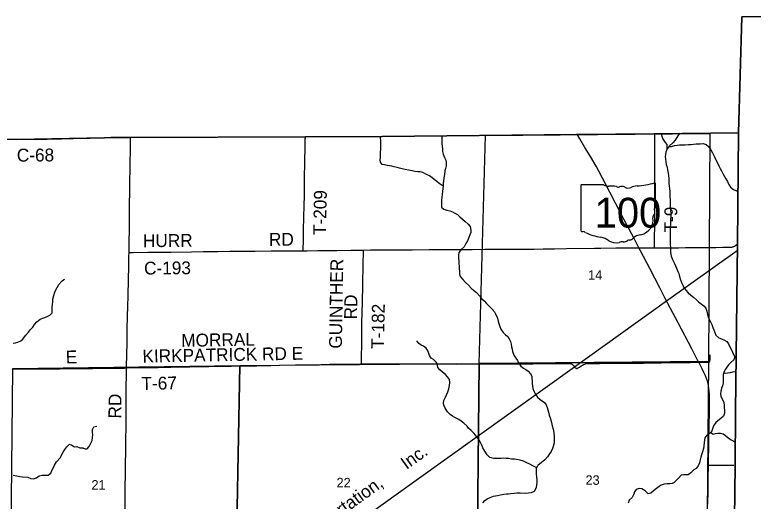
# Model space of a CAD drawing. Extents: x 1584893 to 1934202, y 663575 to 1091909.
# Drawn here: x 1852245 to 1869452, y 976938 to 988278 of the extents above; entities that cross this region are included whole.
import ezdxf

# ---------------------------------------------------------------- set-up
doc = ezdxf.new("R2010")
doc.units = 0
for name, color, linetype in [('GM_X_Adjacent_County', 7, 'Continuous'), ('GM_X_County', 7, 'Continuous'), ('GM_X_County_Road', 7, 'Continuous'), ('GM_X_County_Road_Text', 7, 'Continuous'), ('GM_X_Minor_River', 7, 'Continuous'), ('GM_X_Rail_Line', 7, 'Continuous'), ('GM_X_Rail_Line_Text', 7, 'Continuous'), ('GM_X_Section', 7, 'Continuous'), ('GM_X_Section_Text', 7, 'Continuous'), ('GM_X_State_Location', 7, 'Continuous'), ('GM_X_State_Route', 7, 'Continuous'), ('GM_X_State_Shield', 7, 'Continuous'), ('GM_X_Township', 7, 'Continuous'), ('GM_X_Township_Road', 7, 'Continuous'), ('GM_X_Township_Road_Text', 7, 'Continuous')]:
    doc.layers.add(name, color=color, linetype=linetype)

msp = doc.modelspace()

# ---------------------------------------------------------------- linework, layer by layer
at = {"layer": 'GM_X_Adjacent_County'}
for points in [[(1847071, 963938), (1852487, 963992), (1853408, 964004), (1853786, 964009), (1855618, 964050), (1860298, 964101), (1862894, 964131), (1865546, 964151), (1868643, 964155), (1868654, 967077), (1868896, 971111), (1868903, 971230), (1868993, 974454), (1868995, 974673), (1869028, 977767), (1869041, 979034), (1869083, 982941), (1869110, 985528), (1869183, 988230), (1871661, 988243)], [(1879625, 988278), (1878309, 988257), (1877944, 988247), (1877300, 988258), (1875677, 988261), (1871661, 988243), (1869183, 988230), (1869110, 985528), (1867146, 985506), (1865333, 985487), (1860805, 985437), (1859023, 985435), (1854939, 985417), (1854489, 985417), (1854335, 985412), (1852293, 985374), (1849534, 985395)]]:
    msp.add_lwpolyline(points, dxfattribs=at)
at = {"layer": 'GM_X_County'}
msp.add_lwpolyline([(1849534, 985395), (1852293, 985374), (1854335, 985412), (1854489, 985417), (1854939, 985417), (1859023, 985435), (1860805, 985437), (1865333, 985487), (1867146, 985506), (1869110, 985528), (1869083, 982941), (1869041, 979034), (1869028, 977767), (1868995, 974673)], dxfattribs=at)
at = {"layer": 'GM_X_County_Road'}
for points in [[(1852292, 985375), (1852327, 985375), (1852409, 985376), (1852721, 985377), (1852999, 985381), (1853141, 985382), (1853271, 985385), (1853333, 985387), (1853460, 985391), (1853608, 985395), (1853805, 985401), (1854002, 985405), (1854183, 985408), (1854330, 985410), (1854544, 985418), (1854828, 985423), (1854938, 985423)], [(1854908, 982736), (1854909, 982792), (1854910, 982989), (1854915, 983268), (1854918, 983563), (1854922, 983891), (1854924, 984121), (1854928, 984383), (1854932, 984695), (1854941, 985253), (1854942, 985335), (1854942, 985354), (1854941, 985366), (1854941, 985379), (1854939, 985401), (1854938, 985423)], [(1860368, 982794), (1860536, 982795), (1861062, 982799), (1861505, 982801), (1861899, 982803), (1862112, 982804), (1862408, 982805), (1862670, 982807), (1862900, 982807), (1863196, 982811), (1863622, 982814), (1863967, 982816), (1864345, 982817), (1864558, 982819), (1864820, 982823), (1865099, 982827), (1865756, 982836), (1865904, 982838), (1866248, 982841), (1866482, 982842)], [(1866482, 982842), (1866560, 982842), (1866774, 982843), (1866789, 982843)], [(1866789, 982843), (1866872, 982844), (1867151, 982844), (1867155, 982844)], [(1867155, 982844), (1867315, 982845), (1867709, 982848), (1867873, 982849), (1868004, 982850), (1868217, 982852), (1868316, 982853), (1868398, 982854), (1868577, 982856), (1868734, 982857), (1868874, 982859), (1868923, 982861), (1868953, 982863), (1868968, 982865), (1868988, 982871), (1869003, 982877), (1869020, 982887), (1869035, 982896), (1869076, 982927)], [(1854850, 980044), (1854851, 980102), (1854856, 980331), (1854861, 980659), (1854867, 980932), (1854874, 981268), (1854880, 981463), (1854885, 981742), (1854902, 982431), (1854907, 982644), (1854908, 982736)], [(1854908, 982736), (1854939, 982736), (1855004, 982738), (1855349, 982740), (1855694, 982744), (1855891, 982746), (1856367, 982753), (1856646, 982756), (1856974, 982762), (1857253, 982764), (1857844, 982767), (1858222, 982771), (1858829, 982775), (1858968, 982777)], [(1858968, 982777), (1859059, 982778), (1859305, 982781), (1859748, 982786), (1860077, 982791), (1860368, 982794)], [(1852210, 980019), (1852468, 980021), (1852675, 980022), (1852979, 980025), (1853301, 980027), (1853585, 980030), (1853861, 980034), (1854057, 980035), (1854396, 980038), (1854636, 980041), (1854799, 980042), (1854850, 980044)], [(1854798, 974712), (1854799, 974791), (1854802, 975082), (1854804, 975281), (1854804, 975393), (1854804, 975492), (1854807, 975689), (1854810, 975984), (1854812, 976295), (1854813, 976486), (1854817, 976775), (1854816, 976957), (1854817, 977075), (1854820, 977198), (1854826, 977641), (1854829, 977874), (1854833, 978035), (1854834, 978248), (1854839, 978806), (1854840, 979085), (1854841, 979338), (1854844, 979560), (1854848, 979920), (1854850, 980044)]]:
    msp.add_lwpolyline(points, dxfattribs=at)
at = {"layer": 'GM_X_Minor_River'}
for points in [[(1862225, 984296), (1862202, 984299), (1862133, 984347), (1862078, 984392), (1862021, 984437), (1861970, 984473), (1861907, 984520), (1861838, 984558), (1861753, 984598), (1861695, 984613), (1861635, 984618), (1861570, 984627), (1861508, 984639), (1861428, 984656), (1861345, 984672), (1861271, 984688), (1861213, 984701), (1861158, 984716), (1861086, 984734), (1861034, 984745), (1860979, 984756), (1860923, 984765), (1860861, 984777), (1860809, 984786), (1860765, 984845), (1860762, 984897), (1860767, 984951), (1860768, 985023), (1860771, 985077), (1860773, 985139), (1860774, 985196), (1860775, 985246), (1860774, 985314), (1860768, 985438)], [(1862193, 985454), (1862194, 985336), (1862199, 985276), (1862204, 985206), (1862208, 985152), (1862213, 985087), (1862224, 985025), (1862258, 984954), (1862291, 984887), (1862296, 984831), (1862294, 984755), (1862281, 984697), (1862270, 984637), (1862258, 984555), (1862246, 984477), (1862235, 984405), (1862227, 984337), (1862224, 984285), (1862219, 984225), (1862211, 984155), (1862204, 984095), (1862195, 984019), (1862191, 983967), (1862185, 983858), (1862192, 983796), (1862239, 983743), (1862312, 983719), (1862384, 983704), (1862445, 983683), (1862499, 983653), (1862558, 983618), (1862619, 983571), (1862676, 983511), (1862737, 983462), (1862807, 983398), (1862854, 983345), (1862872, 983257), (1862869, 983204), (1862852, 983145), (1862829, 983085), (1862793, 983008), (1862758, 982942), (1862714, 982871), (1862649, 982804), (1862595, 982735), (1862584, 982673), (1862583, 982605), (1862589, 982534), (1862596, 982478), (1862601, 982416), (1862603, 982360), (1862604, 982292), (1862608, 982223), (1862631, 982167), (1862684, 982107), (1862750, 982036), (1862815, 981972), (1862880, 981903), (1862935, 981859), (1863002, 981806), (1863074, 981728), (1863123, 981667), (1863183, 981606), (1863238, 981546), (1863306, 981479), (1863363, 981425), (1863422, 981352), (1863452, 981291), (1863491, 981202), (1863507, 981138), (1863522, 981081), (1863545, 981012), (1863571, 980952), (1863626, 980874), (1863680, 980817), (1863734, 980778), (1863768, 980725), (1863795, 980662), (1863810, 980600), (1863820, 980537), (1863833, 980481), (1863844, 980427), (1863876, 980344), (1863921, 980269), (1863956, 980216), (1863990, 980155), (1864039, 980090), (1864098, 980038), (1864157, 980007), (1864210, 979968), (1864265, 979908), (1864290, 979856), (1864297, 979796), (1864299, 979741), (1864302, 979691), (1864311, 979617), (1864320, 979566), (1864340, 979502), (1864383, 979421), (1864427, 979366), (1864488, 979312)], [(1867449, 985155), (1867446, 985250), (1867407, 985303), (1867373, 985347), (1867344, 985395), (1867330, 985439), (1867317, 985510)], [(1867737, 985515), (1867633, 985357), (1867575, 985293), (1867503, 985223), (1867449, 985155), (1867416, 985076), (1867404, 985022), (1867402, 984972), (1867406, 984908), (1867412, 984850), (1867426, 984791), (1867444, 984725), (1867456, 984661), (1867472, 984584), (1867480, 984526), (1867484, 984468), (1867486, 984410), (1867488, 984346), (1867492, 984293), (1867498, 984229), (1867506, 984159), (1867508, 984093), (1867512, 984032), (1867514, 983966), (1867516, 983910), (1867516, 983840), (1867520, 983779), (1867524, 983715), (1867530, 983651), (1867530, 983583), (1867526, 983508), (1867526, 983446), (1867522, 983392), (1867518, 983332), (1867516, 983281), (1867516, 983221), (1867514, 983161), (1867514, 983109), (1867516, 983038), (1867516, 982978), (1867518, 982922), (1867524, 982844), (1867528, 982735), (1867540, 982651), (1867572, 982569), (1867612, 982492), (1867644, 982426), (1867666, 982370), (1867698, 982296), (1867718, 982245), (1867734, 982175), (1867754, 982101), (1867780, 982039), (1867808, 981972), (1867838, 981920), (1867885, 981858), (1867937, 981792), (1867995, 981743), (1868059, 981693), (1868127, 981633), (1868180, 981589), (1868240, 981541), (1868302, 981494), (1868346, 981436), (1868368, 981370), (1868388, 981290), (1868402, 981235), (1868424, 981175), (1868456, 981119), (1868484, 981055), (1868514, 980988), (1868534, 980934), (1868559, 980870), (1868583, 980808), (1868647, 980749), (1868713, 980723), (1868779, 980693), (1868839, 980661), (1868876, 980607), (1868910, 980535), (1868942, 980468), (1868970, 980414), (1868996, 980356), (1869020, 980304), (1869002, 980231), (1868932, 980169), (1868879, 980117), (1868837, 980065), (1868803, 980015), (1868775, 979962), (1868755, 979894), (1868749, 979820), (1868753, 979762), (1868751, 979695), (1868737, 979631), (1868715, 979575), (1868696, 979503), (1868690, 979440), (1868694, 979388), (1868732, 979318), (1868769, 979250)], [(1867489, 985206), (1867545, 985207), (1867619, 985227), (1867679, 985235), (1867732, 985243), (1867814, 985249), (1867864, 985247), (1867940, 985251), (1868009, 985255), (1868059, 985261), (1868119, 985267), (1868169, 985271), (1868219, 985273), (1868288, 985277), (1868356, 985257), (1868406, 985207), (1868462, 985126), (1868500, 985062), (1868542, 984978), (1868582, 984900), (1868619, 984823), (1868651, 984759), (1868679, 984697), (1868709, 984641), (1868741, 984580), (1868783, 984508), (1868817, 984452), (1868849, 984388), (1868887, 984321), (1868921, 984261), (1868990, 984207), (1869099, 984161)], [(1852207, 980620), (1852259, 980634), (1852319, 980647), (1852384, 980674), (1852437, 980717), (1852499, 980804), (1852566, 980881), (1852615, 980940), (1852663, 980999), (1852708, 981058), (1852759, 981117), (1852838, 981180), (1852921, 981214), (1852983, 981235), (1853066, 981273), (1853117, 981333), (1853120, 981383), (1853120, 981467), (1853123, 981523), (1853129, 981585), (1853136, 981651), (1853154, 981735), (1853180, 981813), (1853205, 981866), (1853232, 981920), (1853275, 981991), (1853339, 982068), (1853390, 982107), (1853410, 982115)], [(1864408, 977720), (1864320, 977762), (1864243, 977803), (1864161, 977839), (1864100, 977868), (1864021, 977892), (1863939, 977912), (1863887, 977919), (1863819, 977922), (1863751, 977932), (1863698, 977937), (1863642, 977938), (1863582, 977935), (1863524, 977933), (1863462, 977932), (1863408, 977935), (1863314, 977955), (1863249, 978017), (1863197, 978106), (1863155, 978181), (1863126, 978244), (1863096, 978305), (1863055, 978376), (1863010, 978439), (1862946, 978520), (1862878, 978588), (1862821, 978639), (1862784, 978690), (1862709, 978758), (1862646, 978805), (1862593, 978840), (1862502, 978888), (1862441, 978924), (1862390, 978961), (1862329, 979018), (1862271, 979104), (1862246, 979175), (1862237, 979229), (1862241, 979283), (1862278, 979360), (1862314, 979432), (1862337, 979488), (1862362, 979555), (1862378, 979639), (1862382, 979709), (1862371, 979772), (1862330, 979837), (1862272, 979902), (1862211, 979945), (1862150, 980001), (1862105, 980058), (1862094, 980112), (1862069, 980173), (1862005, 980238), (1861946, 980276), (1861911, 980335), (1861886, 980403), (1861864, 980458), (1861833, 980509), (1861772, 980554), (1861718, 980573), (1861657, 980615), (1861610, 980680)], [(1868765, 979927), (1868803, 979926), (1868855, 979932), (1868925, 979940), (1868978, 979952), (1869055, 979964)], [(1864488, 979312), (1864592, 979240), (1864624, 979182), (1864648, 979124), (1864664, 979068), (1864678, 979013), (1864698, 978945), (1864726, 978857), (1864748, 978772), (1864770, 978694), (1864788, 978616), (1864806, 978539), (1864812, 978437), (1864814, 978373), (1864810, 978297), (1864790, 978216), (1864774, 978164), (1864742, 978096), (1864704, 978040), (1864656, 977975), (1864599, 977903), (1864432, 977769)], [(1868769, 979250), (1868773, 979165), (1868777, 979113), (1868783, 979061), (1868780, 978987), (1868758, 978924), (1868696, 978868), (1868630, 978812), (1868578, 978772), (1868527, 978692), (1868505, 978629), (1868479, 978557), (1868419, 978503), (1868367, 978481), (1868327, 978412), (1868317, 978358), (1868309, 978304), (1868302, 978220), (1868296, 978166), (1868268, 978087), (1868248, 978017), (1868230, 977967), (1868214, 977901), (1868200, 977834), (1868166, 977760), (1868124, 977704), (1868069, 977668), (1867997, 977601), (1867937, 977555), (1867879, 977553), (1867827, 977555), (1867776, 977543), (1867710, 977475), (1867658, 977421), (1867612, 977371), (1867561, 977350), (1867507, 977346), (1867445, 977344), (1867377, 977338), (1867309, 977310), (1867258, 977280), (1867198, 977234), (1867132, 977180), (1867064, 977124), (1867005, 977110), (1866933, 977178), (1866857, 977226), (1866795, 977234), (1866726, 977212), (1866688, 977158), (1866672, 977102), (1866632, 977027), (1866558, 976965), (1866536, 976893)], [(1853022, 977546), (1853083, 977595), (1853112, 977651), (1853145, 977722), (1853174, 977780), (1853214, 977857), (1853308, 977959), (1853335, 978011), (1853371, 978080), (1853410, 978146), (1853457, 978209), (1853517, 978270), (1853576, 978247), (1853639, 978209), (1853693, 978214), (1853763, 978185), (1853831, 978183), (1853884, 978160), (1853936, 978161), (1853979, 978216), (1854009, 978272), (1854048, 978351), (1854056, 978421), (1854063, 978485), (1854060, 978547), (1854056, 978610), (1854089, 978673), (1854161, 978686)], [(1868461, 978541), (1868519, 978503), (1868574, 978513), (1868628, 978525), (1868690, 978525), (1868752, 978509), (1868804, 978473), (1868871, 978418), (1868941, 978368), (1869037, 978316)], [(1863250, 976990), (1863323, 977028), (1863399, 977055), (1863496, 977075), (1863560, 977086), (1863640, 977100), (1863700, 977107), (1863750, 977112), (1863802, 977115), (1863884, 977123), (1863944, 977130), (1864020, 977130), (1864142, 977128), (1864210, 977132), (1864283, 977139), (1864353, 977171), (1864399, 977257), (1864412, 977318), (1864418, 977378), (1864417, 977437), (1864408, 977509), (1864404, 977571), (1864401, 977638), (1864400, 977704), (1864432, 977769)], [(1852210, 977543), (1852292, 977532), (1852363, 977512), (1852425, 977503), (1852551, 977500), (1852622, 977468), (1852682, 977459), (1852754, 977484), (1852815, 977531), (1852886, 977545), (1852952, 977548), (1853022, 977546)], [(1863150, 976900), (1863197, 976953), (1863250, 976990)]]:
    msp.add_lwpolyline(points, dxfattribs=at)
at = {"layer": 'GM_X_Rail_Line'}
msp.add_lwpolyline([(1856303, 973619), (1858134, 974941), (1861544, 977391), (1865288, 980070), (1867429, 981609), (1869080, 982786)], dxfattribs=at)
at = {"layer": 'GM_X_Section'}
for points in [[(1863210, 985461), (1868438, 985512), (1868412, 980193), (1863067, 980146)], [(1852199, 980028), (1857493, 980105), (1857385, 974712), (1852149, 974677)], [(1857493, 980105), (1863067, 980146), (1863013, 974788), (1857385, 974712)], [(1863067, 980146), (1868412, 980193), (1868365, 974835), (1863013, 974788)]]:
    msp.add_lwpolyline(points, close=True, dxfattribs=at)
at = {"layer": 'GM_X_State_Route'}
msp.add_lwpolyline([(1868398, 976870), (1868401, 977182), (1868405, 977477), (1868408, 977781), (1868410, 977952), (1868415, 978165), (1868418, 978362), (1868425, 978756), (1868430, 978969), (1868431, 979149), (1868432, 979215), (1868433, 979330), (1868431, 979428), (1868426, 979510), (1868419, 979576), (1868410, 979624), (1868400, 979673), (1868383, 979736), (1868362, 979799), (1868338, 979860), (1868304, 979935), (1868261, 980024), (1868181, 980178), (1868163, 980213), (1868019, 980489), (1867700, 981100), (1867525, 981434), (1867395, 981681), (1867274, 981914), (1867039, 982364), (1866826, 982771), (1866789, 982843), (1866682, 983048), (1866386, 983615), (1866112, 984145), (1865857, 984633), (1865793, 984748), (1865659, 984974), (1865531, 985184), (1865415, 985382), (1865357, 985482)], dxfattribs=at)
at = {"layer": 'GM_X_State_Shield'}
for p, q in [((1865436, 984298), (1865436, 983242)), ((1865963, 984316), (1865454, 984316)), ((1867177, 983790), (1867177, 984343)), ((1867176, 983790), (1867177, 983790))]:
    msp.add_line(p, q, dxfattribs=at)
for centre, major_axis, start_param, end_param in [((1865456, 984300), (20.2, 0), 1.712693, 3.28349), ((1866085, 984439), (196, 0), 4.042523, 4.731795), ((1866149, 983723), (702, 0), 1.404758, 1.657858), ((1866309, 984306), (56.4, 0), 3.836095, 5.185415), ((1866392, 984184), (117, 0), 0.950623, 2.079405), ((1866543, 984351), (141, 0), 4.081561, 5.145723), ((1866792, 983994), (371, 0), 1.699011, 2.107814), ((1866557, 985757), (1845, 0), 4.814394, 5.042369), ((1867157, 984345), (19.4, 0), 6.141152, 7.989035), ((1867172, 983749), (30, 0), 1.883978, 3.671073), ((1866981, 983679), (180, 0), 5.934695, 6.695948), ((1867156, 983788), (20.7, 0), 5.05454, 6.418171), ((1866660, 983488), (462, 0), 5.101752, 6.440018), ((1867246, 983559), (131, 0), 2.387724, 3.262537), ((1865457, 983239), (20.3, 0), 3.00124, 4.508301), ((1865460, 983347), (155, 0), 4.665946, 4.897461), ((1865491, 983181), (56, 0), 0.519207, 1.627899), ((1866198, 984130), (1333, 0), 4.195997, 4.488961), ((1865801, 982767), (417, 0), 0.823519, 1.323587), ((1866252, 983175), (265, 0), 4.026481, 4.996735), ((1866424, 983096), (141, 0), 4.691044, 5.507374), ((1866551, 982994), (39.7, 0), 1.147584, 2.315152), ((1866534, 983139), (149, 0), 4.937069, 5.64225), ((1866855, 982945), (253, 0), 1.647645, 2.488434), ((1866404, 982810), (217, 0), 1.495662, 1.94098)]:
    msp.add_ellipse(centre, major_axis=major_axis, ratio=0.8, start_param=start_param, end_param=end_param, dxfattribs=at)
at = {"layer": 'GM_X_Township'}
msp.add_lwpolyline([(1849534, 985395), (1852293, 985374), (1854335, 985412), (1854489, 985417), (1854939, 985417), (1859023, 985435), (1860805, 985437), (1865333, 985487), (1867146, 985506), (1869110, 985528), (1869083, 982941), (1869041, 979034), (1869028, 977767), (1868995, 974673)], dxfattribs=at)
at = {"layer": 'GM_X_Township_Road'}
for points in [[(1858968, 982777), (1858969, 982815), (1858971, 983011), (1858976, 983273), (1858988, 983829), (1858993, 984058), (1858999, 984451), (1859003, 984860), (1859008, 985188), (1859009, 985302), (1859012, 985367), (1859014, 985388), (1859017, 985407), (1859023, 985434), (1859026, 985447)], [(1867155, 982844), (1867155, 982890), (1867155, 983076), (1867156, 983356), (1867157, 983597), (1867160, 984041), (1867159, 984254), (1867160, 984468), (1867161, 984698), (1867161, 984895), (1867161, 985191), (1867160, 985386), (1867159, 985504)], [(1846795, 985381), (1847244, 985388), (1847441, 985388), (1847819, 985390), (1848098, 985390), (1848246, 985390), (1848475, 985390), (1848623, 985392), (1848820, 985392), (1852292, 985375)], [(1860320, 980138), (1860321, 980164), (1860321, 980196), (1860324, 980278), (1860331, 980623), (1860336, 981070), (1860342, 981360), (1860345, 981557), (1860353, 982001), (1860362, 982446), (1860368, 982776), (1860368, 982794)], [(1868430, 980188), (1868434, 980191), (1868437, 980196), (1868441, 980203), (1868444, 980216), (1868445, 980236), (1868445, 980263), (1868446, 980281), (1868446, 980301), (1868447, 980319), (1868451, 980347)], [(1854850, 980044), (1854865, 980044), (1855392, 980054), (1855589, 980058), (1855884, 980063), (1856179, 980068), (1856327, 980071), (1856770, 980079), (1857032, 980083), (1857295, 980088), (1857606, 980092), (1857885, 980097), (1858214, 980102), (1858410, 980106), (1858788, 980114), (1859083, 980118), (1859378, 980124), (1859575, 980129), (1859756, 980131), (1860067, 980134), (1860264, 980136), (1860320, 980138)], [(1860320, 980138), (1860395, 980139), (1860560, 980142), (1860822, 980142), (1860970, 980140), (1861149, 980138), (1861403, 980139), (1861692, 980140), (1861938, 980138), (1862151, 980138), (1862528, 980136), (1863103, 980139), (1863300, 980139), (1863464, 980139), (1863825, 980142), (1864153, 980144), (1864317, 980144), (1864432, 980145), (1864661, 980146), (1864760, 980147), (1864973, 980148), (1865137, 980151), (1865170, 980150), (1865186, 980147), (1865202, 980143), (1865217, 980137), (1865231, 980129), (1865244, 980119), (1865256, 980107), (1865287, 980069), (1865298, 980057), (1865309, 980046), (1865316, 980041), (1865322, 980039), (1865330, 980036), (1865337, 980035), (1865347, 980035), (1865352, 980036), (1865360, 980039), (1865373, 980044), (1865388, 980054), (1865402, 980062), (1865442, 980091), (1865470, 980109), (1865499, 980124), (1865529, 980136), (1865561, 980145), (1865593, 980149), (1865647, 980150), (1865872, 980152), (1866135, 980155), (1866489, 980159), (1866702, 980160), (1866898, 980160), (1867086, 980164), (1867306, 980165), (1867731, 980173), (1867983, 980175), (1868181, 980178)], [(1868181, 980178), (1868235, 980178), (1868382, 980180), (1868401, 980181), (1868418, 980183), (1868423, 980184), (1868429, 980187), (1868430, 980188)], [(1868408, 977781), (1868438, 977781), (1868494, 977781), (1868594, 977779), (1868640, 977779), (1868695, 977778), (1868803, 977778), (1869001, 977778)]]:
    msp.add_lwpolyline(points, dxfattribs=at)

# ---------------------------------------------------------------- texts
at = {"layer": 'GM_X_County_Road_Text'}
for s, rotation, p in [('C-68', 0.3419, (1852294, 984855)), ('RD', 0.4955, (1858169, 982890)), ('HURR', 0.492, (1855233, 982859)), ('C-193', 0.5504, (1855259, 982220)), ('E', 1.1227, (1853436, 980149)), ('RD', 89.5114, (1854727, 978864))]:
    msp.add_text(s, height=300, rotation=rotation, dxfattribs=at).set_placement(p)
at = {"layer": 'GM_X_Rail_Line_Text'}
for s, rotation, p in [('Inc.', 35.6557, (1861374, 977664)), ('Transportation,', 35.7108, (1858674, 975730))]:
    msp.add_text(s, height=299, rotation=rotation, dxfattribs=at).set_placement(p)
at = {"layer": 'GM_X_Section_Text'}
for s, p in [('14', (1865606, 982103)), ('23', (1865545, 977321)), ('21', (1854032, 977208)), ('22', (1859743, 977261))]:
    msp.add_text(s, height=221, rotation=0, dxfattribs=at).set_placement(p)
at = {"layer": 'GM_X_State_Location'}
for s in ['s', 'r']:
    msp.add_text(s, height=1, dxfattribs=at).set_placement((1866287, 983700))
msp.add_text('100', height=1, rotation=0, dxfattribs=at).set_placement((1865934, 983627))
at = {"layer": 'GM_X_State_Shield'}
msp.add_text('100', height=696.1, dxfattribs=at).set_placement((1865757, 983316))
at = {"layer": 'GM_X_Township_Road_Text'}
for s, rotation, p in [('T-209', 88.871, (1859498, 983140)), ('T-9', 89.5181, (1867678, 983202)), ('GUINTHER', 89.0627, (1859867, 980492)), ('RD', 89.018, (1860219, 981174)), ('T-182', 88.8773, (1860849, 980489)), ('MORRAL', 0.9626, (1856127, 980536)), ('KIRKPATRICK RD E', 1.0408, (1855223, 980169)), ('T-67', 1.0602, (1855200, 979532))]:
    msp.add_text(s, height=300, rotation=rotation, dxfattribs=at).set_placement(p)

doc.saveas('drawing.dxf')
